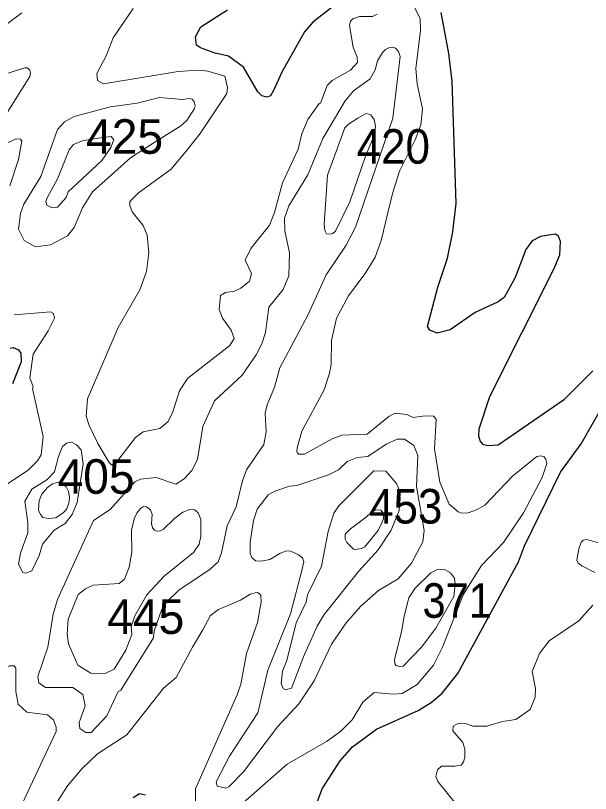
# Model space of a CAD drawing. Extents: x 499.9 to 555.3, y 9281.5 to 9336.8.
# Drawn here: x 543.063 to 545.724, y 9322.551 to 9326.154 of the extents above; entities that cross this region are included whole.
import ezdxf

# ---------------------------------------------------------------- set-up
doc = ezdxf.new("R2010")
doc.units = 0
doc.header["$LTSCALE"] = 0.064
doc.layers.add('1', color=7, linetype='Continuous', lineweight=25)
doc.layers.add('2', color=7, linetype='Continuous', lineweight=13)
doc.layers.add('21', color=7, linetype='Continuous')

msp = doc.modelspace()

# ---------------------------------------------------------------- linework, layer by layer
at = {"layer": '1'}
for points in [[(544.5287, 9326.1933), (544.439, 9326.1227), (544.4008, 9326.0781), (544.2953, 9325.8912), (544.2576, 9325.8066), (544.2426, 9325.7829), (544.2262, 9325.7766), (544.2022, 9325.7818), (544.184, 9325.8005), (544.1174, 9325.9155), (544.0486, 9325.966), (543.9862, 9325.9797), (543.9197, 9326.0039), (543.9011, 9326.0169), (543.8952, 9326.0548), (543.9209, 9326.1023), (544.0435, 9326.1811)], [(545.7352, 9324.509), (545.5991, 9324.372), (545.2972, 9324.1635), (545.2514, 9324.1604), (545.2286, 9324.1654), (545.213, 9324.1836), (545.2065, 9324.2059), (545.2085, 9324.2395), (545.2583, 9324.39), (545.5537, 9324.9796), (545.5816, 9325.0461), (545.5847, 9325.108), (545.5754, 9325.132), (545.561, 9325.1422), (545.4933, 9325.1313), (545.4539, 9325.1113), (545.4249, 9325.0702), (545.375, 9324.9409), (545.3242, 9324.8485), (545.2967, 9324.8288), (545.1909, 9324.7782), (545.0747, 9324.6981), (545.0144, 9324.6828), (544.9803, 9324.6969), (544.9702, 9324.7136), (545.0173, 9324.8955), (545.0622, 9325.0302), (545.0866, 9325.1526), (545.1026, 9325.2828), (545.0835, 9325.8505), (545.069, 9325.9787), (545.0325, 9326.1688)], [(543.0383, 9324.6136), (543.0524, 9324.6164), (543.076, 9324.6054), (543.088, 9324.5903), (543.0886, 9324.5509), (543.0492, 9324.448)], [(544.4325, 9322.4383), (544.482, 9322.5719), (544.5652, 9322.7015), (544.622, 9322.7675), (544.7343, 9322.8484), (544.9268, 9322.936), (544.9864, 9322.973), (545.0369, 9323.0157), (545.11, 9323.106), (545.3913, 9323.6241), (545.4194, 9323.6987), (545.5845, 9324.0386), (545.6808, 9324.1706), (545.7827, 9324.3488)], [(543.6076, 9322.5331), (543.6373, 9322.5512), (543.6641, 9322.5446)]]:
    msp.add_lwpolyline(points, dxfattribs=at)
at = {"layer": '2'}
for points in [[(544.6249, 9326.0083), (544.644, 9325.9618), (544.6453, 9325.9361), (544.6139, 9325.9016), (544.5287, 9325.8531), (544.5047, 9325.8303), (544.4743, 9325.7484), (544.4675, 9325.7462), (544.4153, 9325.6726), (544.3882, 9325.6061), (544.3716, 9325.5345), (544.2984, 9325.379), (544.261, 9325.2417), (544.2389, 9325.1826), (544.152, 9325.0754), (544.1263, 9325.0216), (544.1552, 9324.9599), (544.1461, 9324.9233), (544.1051, 9324.8911), (544.076, 9324.8782), (544.0341, 9324.8713), (544.0116, 9324.8567), (544.0051, 9324.792), (544.0205, 9324.7524), (544.0604, 9324.6974), (544.0755, 9324.6576), (544.0553, 9324.6251), (543.8601, 9324.4739), (543.8213, 9324.4156), (543.7897, 9324.3139), (543.7672, 9324.2719), (543.7305, 9324.2417), (543.6535, 9324.2256), (543.6175, 9324.1996), (543.5404, 9324.0988), (543.5282, 9324.0809), (543.5194, 9324.0733), (543.5063, 9324.0731), (543.4955, 9324.0837), (543.4436, 9324.1714), (543.4032, 9324.2551), (543.3901, 9324.2979), (543.3964, 9324.3791), (543.5385, 9324.7088), (543.6383, 9324.8829), (543.6686, 9324.9688), (543.6797, 9325.0547), (543.6719, 9325.1368), (543.653, 9325.1813), (543.6026, 9325.2453), (543.5926, 9325.274), (543.5923, 9325.2927), (543.6316, 9325.3322), (543.7828, 9325.4422), (543.8589, 9325.5332), (543.9172, 9325.6079), (544.0415, 9325.7929), (544.0439, 9325.8205), (544.0311, 9325.8725), (543.9527, 9325.8964), (543.9107, 9325.9011), (543.8159, 9325.8943), (543.4697, 9325.8381), (543.4428, 9325.8526), (543.4396, 9325.8856), (543.482, 9325.9677), (543.5155, 9326.0503), (543.6067, 9326.1869)], [(544.0272, 9322.4295), (544.3203, 9322.6869), (544.5019, 9322.7911), (544.567, 9322.8383), (544.6203, 9322.8919), (544.6699, 9322.9744), (544.7225, 9323.0191), (544.8106, 9323.0113), (544.8519, 9323.0144), (544.9211, 9323.0558), (544.9971, 9323.1451), (545.0388, 9323.2283), (545.1364, 9323.4748), (545.2199, 9323.6074), (545.3218, 9323.7129), (545.4141, 9323.8508), (545.5005, 9324.0139), (545.5223, 9324.0791), (545.5171, 9324.0972), (545.5096, 9324.1106), (545.4942, 9324.1152), (545.4753, 9324.1117), (545.3631, 9324.0213), (545.2347, 9323.8866), (545.1965, 9323.8643), (545.1583, 9323.851), (545.1265, 9323.85), (545.1111, 9323.8561), (545.0692, 9323.8916), (545.0269, 9323.9927), (545.0024, 9324.1475), (545.0102, 9324.2847), (544.9973, 9324.2984), (544.9578, 9324.3002), (544.9034, 9324.2924), (544.8742, 9324.3068), (544.8191, 9324.3118), (544.7908, 9324.2976), (544.6911, 9324.2145), (544.5727, 9324.2111), (544.5281, 9324.1937), (544.4003, 9324.1221), (544.376, 9324.1223), (544.3679, 9324.1275), (544.3655, 9324.1354), (544.366, 9324.1521), (544.3885, 9324.2291), (544.4911, 9324.4207), (544.5167, 9324.497), (544.5233, 9324.5377), (544.525, 9324.649), (544.5488, 9324.7523), (544.6035, 9324.8559), (544.685, 9324.9639), (544.727, 9325.0356), (544.7556, 9325.112), (544.807, 9325.3302), (544.8398, 9325.4328), (544.9122, 9325.5784), (544.9388, 9325.6476), (544.9466, 9325.7225), (544.9212, 9325.8378), (544.9164, 9325.9093), (544.9369, 9326.0854), (544.9352, 9326.1401), (544.9099, 9326.1911)], [(543.0925, 9326.166), (542.9556, 9326.0655), (542.8864, 9326.0303), (542.8583, 9326.0273), (542.7971, 9326.0367), (542.7721, 9326.0767), (542.7648, 9326.1236), (542.7679, 9326.1728)], [(544.7369, 9326.1597), (544.7154, 9326.1502)], [(544.7154, 9326.1502), (544.6555, 9326.1496), (544.6243, 9326.1388), (544.6131, 9326.1285), (544.608, 9326.1082), (544.6249, 9326.0083)], [(543.0129, 9325.8824), (543.1055, 9325.9126), (543.1174, 9325.9122), (543.1277, 9325.9037), (543.132, 9325.8891), (543.1295, 9325.8713), (542.9964, 9325.6604)], [(542.9896, 9325.5494), (543.0656, 9325.5836), (543.0865, 9325.581), (543.0928, 9325.5724), (543.0762, 9325.487), (543.0366, 9325.3659)], [(543.0567, 9324.7671), (543.2253, 9324.781), (543.2391, 9324.7747), (543.243, 9324.7526), (543.2143, 9324.6936), (543.1445, 9324.5851), (543.1296, 9324.4761), (543.1438, 9324.4343), (543.1407, 9324.4261), (543.1903, 9324.2037)], [(543.1903, 9324.2037), (543.1816, 9324.1197), (543.1644, 9324.0919), (543.1233, 9324.0494), (542.996, 9323.9649), (542.9687, 9323.9204)], [(545.7822, 9323.7057), (545.7065, 9323.7266), (545.69, 9323.7244), (545.6803, 9323.7154), (545.6699, 9323.6836), (545.6616, 9323.6321), (545.6674, 9323.6181), (545.6838, 9323.605), (545.7438, 9323.5744)], [(543.9305, 9323.3094), (543.9649, 9323.3746), (544.0027, 9323.4024), (544.1043, 9323.447), (544.1493, 9323.4742), (544.1715, 9323.4803), (544.1832, 9323.4821), (544.1909, 9323.4775), (544.1975, 9323.4685), (544.1998, 9323.4369), (544.1827, 9323.3422), (544.132, 9323.1998), (544.105, 9323.0576), (544.0884, 9323.0084), (543.8951, 9322.5727), (543.8946, 9322.4294)], [(545.7347, 9323.4226), (545.6708, 9323.3506), (545.5334, 9323.2573), (545.4874, 9323.1998), (545.4544, 9323.1157), (545.4701, 9323.0366), (545.4687, 9322.997), (545.4449, 9322.9402), (545.3779, 9322.8936), (545.3175, 9322.8847), (545.2442, 9322.8633), (545.1802, 9322.863), (545.1503, 9322.8742), (545.1095, 9322.8744)], [(543.222, 9322.4589), (543.3037, 9322.5872), (543.3715, 9322.6661), (543.4427, 9322.7342), (543.5773, 9322.823), (543.7482, 9323.0382), (543.8063, 9323.0888), (543.8821, 9323.2283), (543.9305, 9323.3094)], [(542.2021, 9322.5045), (542.3336, 9322.6297), (542.5889, 9322.807), (542.7846, 9322.9614), (542.9205, 9323.052), (542.9907, 9323.1239), (543.0365, 9323.1426), (543.0571, 9323.1429), (543.0637, 9323.131), (543.0648, 9323.0234), (543.0745, 9322.9649), (543.115, 9322.9271), (543.2102, 9322.9155), (543.2393, 9322.8921), (543.2515, 9322.8584), (543.251, 9322.8379), (542.9945, 9322.2935)], [(545.1095, 9322.8744), (545.0887, 9322.8627), (545.0874, 9322.8416), (545.1331, 9322.7868), (545.1418, 9322.7556), (545.142, 9322.7177)], [(545.142, 9322.7177), (545.1367, 9322.6974), (545.1251, 9322.682), (545.0962, 9322.6771), (545.0344, 9322.6776), (545.0153, 9322.6608), (545.009, 9322.63), (545.0177, 9322.6071), (545.0944, 9322.5113)]]:
    msp.add_lwpolyline(points, dxfattribs=at)
for points in [[(544.3071, 9325.2162), (544.3283, 9325.2734), (544.4153, 9325.4163), (544.4857, 9325.5851), (544.5889, 9325.7586), (544.6271, 9325.8059), (544.705, 9325.8608), (544.7271, 9325.9022), (544.7385, 9325.9435), (544.7617, 9325.9836), (544.775, 9325.9965), (544.7933, 9326.0059), (544.8076, 9326.0081), (544.8213, 9326.0036), (544.8354, 9325.9871), (544.843, 9325.965), (544.8097, 9325.6786), (544.6365, 9325.1733), (544.5937, 9325.0904), (544.5006, 9324.9538), (544.4174, 9324.7699), (544.2868, 9324.5222), (544.262, 9324.4333), (544.2271, 9324.3506), (544.2184, 9324.3132), (544.2223, 9324.2264), (544.2129, 9324.1673), (544.1326, 9324.0502), (544.113, 9323.9987), (544.0843, 9323.8792), (544.0427, 9323.791), (544.0168, 9323.6662), (544.0003, 9323.6241), (543.964, 9323.5901), (543.8183, 9323.4934), (543.7621, 9323.4371), (543.7384, 9323.4004), (543.7048, 9323.3042), (543.7008, 9323.2717), (543.551, 9323.0296), (543.5379, 9323.0231), (543.4851, 9322.9114), (543.4125, 9322.8336), (543.388, 9322.8335), (543.3603, 9322.8524), (543.3569, 9322.8794), (543.385, 9322.9563), (543.3751, 9323.01), (543.328, 9323.0412), (543.2011, 9323.0412), (543.1715, 9323.063), (543.1661, 9323.0931), (543.212, 9323.2284), (543.2374, 9323.3812), (543.2573, 9323.4488), (543.4236, 9323.8151), (543.5015, 9323.8665), (543.6149, 9323.9949), (543.6409, 9324.007), (543.7141, 9324.0152), (543.8055, 9323.9841), (543.8441, 9324.0081), (543.8786, 9324.0474), (543.9045, 9324.0985), (543.93, 9324.2502), (543.9844, 9324.3692), (544.1115, 9324.4888), (544.1759, 9324.583), (544.2029, 9324.6339), (544.2191, 9324.6855), (544.2351, 9324.8026), (544.3019, 9324.8845), (544.3274, 9324.9487), (544.3306, 9325.0547), (544.3101, 9325.1566)], [(543.4187, 9325.3376), (543.5944, 9325.4955), (543.6954, 9325.5603), (543.8277, 9325.6437), (543.8556, 9325.6685), (543.8917, 9325.7229), (543.8942, 9325.7359), (543.8903, 9325.7543), (543.8798, 9325.7672), (543.8679, 9325.7694), (543.8334, 9325.7646), (543.7291, 9325.774), (543.6265, 9325.7485), (543.5032, 9325.7311), (543.3338, 9325.6862), (543.2894, 9325.6621), (543.2577, 9325.6269), (543.1798, 9325.4082), (543.1018, 9325.28), (543.0857, 9325.2376), (543.0771, 9325.1651), (543.1028, 9325.1117), (543.1548, 9325.0827), (543.2244, 9325.0925), (543.304, 9325.1345), (543.3338, 9325.172), (543.3733, 9325.2632)], [(544.6824, 9325.5024), (544.7221, 9325.5978), (544.7284, 9325.6421), (544.7226, 9325.6727), (544.707, 9325.6947), (544.6862, 9325.7007), (544.6476, 9325.6781), (544.6033, 9325.6508), (544.5878, 9325.6332), (544.5064, 9325.4142), (544.4915, 9325.1877), (544.495, 9325.1592), (544.5028, 9325.1433), (544.5163, 9325.141), (544.5316, 9325.1453), (544.5444, 9325.1559), (544.6102, 9325.2919)], [(543.4619, 9325.4825), (543.5043, 9325.5435), (543.5173, 9325.5776), (543.5059, 9325.5943), (543.4456, 9325.5854), (543.3706, 9325.5731), (543.3308, 9325.5567), (543.3107, 9325.5326), (543.2591, 9325.401), (543.2073, 9325.3062), (543.2036, 9325.2925), (543.2075, 9325.2763), (543.2318, 9325.2639), (543.2573, 9325.2667), (543.2965, 9325.3111), (543.3065, 9325.3369)], [(543.242, 9323.7709), (543.2921, 9323.8008), (543.3243, 9323.8436), (543.3479, 9323.8985), (543.3756, 9324.0775), (543.3664, 9324.1421), (543.345, 9324.1654), (543.3216, 9324.1775), (543.2994, 9324.1728), (543.28, 9324.1579), (543.2612, 9324.1125), (543.2438, 9324.0411), (543.2084, 9324.0032), (543.1384, 9323.9609), (543.1054, 9323.9048), (543.1195, 9323.8062), (543.1194, 9323.7579), (543.0862, 9323.6637), (543.0769, 9323.6136), (543.0974, 9323.575), (543.1099, 9323.5719), (543.1376, 9323.5823), (543.172, 9323.6534), (543.1882, 9323.7051)], [(544.3362, 9323.3824), (544.3894, 9323.5892), (544.3969, 9323.6249), (544.391, 9323.6417), (544.3729, 9323.6563), (544.3371, 9323.6737), (544.316, 9323.6745), (544.2861, 9323.6621), (544.2404, 9323.6346), (544.1994, 9323.6271), (544.1737, 9323.629), (544.1559, 9323.6432), (544.1495, 9323.6631), (544.1493, 9323.7146), (544.165, 9323.8157), (544.1816, 9323.8681), (544.2317, 9323.9337), (544.2623, 9323.951), (544.3307, 9323.9739), (544.3656, 9323.9776), (544.5121, 9324.0267), (544.5575, 9324.0501), (544.5982, 9324.0885), (544.6435, 9324.1077), (544.6942, 9324.1115), (544.7789, 9324.1693), (544.8286, 9324.1913), (544.8638, 9324.1919), (544.907, 9324.1627), (544.9256, 9324.1163), (544.918, 9323.9726), (544.9544, 9323.7695), (544.9474, 9323.716), (544.8952, 9323.6177), (544.834, 9323.5449), (544.7431, 9323.4905), (544.6618, 9323.4186), (544.5929, 9323.3421), (544.5249, 9323.2419), (544.4456, 9323.0724), (544.3736, 9322.9667), (544.2752, 9322.8598), (544.1185, 9322.6516), (544.0496, 9322.582), (544.0361, 9322.5754), (543.9967, 9322.5849), (543.9909, 9322.6043), (544.0532, 9322.7232), (544.1841, 9322.9253), (544.2311, 9323.1222)], [(544.479, 9323.6041), (544.5105, 9323.7639), (544.5364, 9323.8487), (544.5592, 9323.8831), (544.7211, 9324.0447), (544.7761, 9324.0437), (544.8255, 9323.9867), (544.8369, 9323.9605), (544.843, 9323.9184), (544.8382, 9323.8612), (544.8017, 9323.7703), (544.7421, 9323.6794), (544.65, 9323.5794), (544.491, 9323.3797), (544.4597, 9323.3263), (544.3963, 9323.1837), (544.3409, 9323.0385), (544.3127, 9323.0307), (544.3019, 9323.0374), (544.2928, 9323.0599), (544.2986, 9323.1174), (544.3179, 9323.1671), (544.3621, 9323.3418), (544.4083, 9323.4366), (544.4137, 9323.471)], [(543.1899, 9323.8298), (543.2152, 9323.8243), (543.2499, 9323.8282), (543.2846, 9323.8527), (543.2996, 9323.8701), (543.3114, 9323.9016), (543.313, 9323.9229), (543.3083, 9323.949), (543.2965, 9323.9719), (543.2807, 9323.9845), (543.2554, 9323.9908), (543.2333, 9323.9845), (543.2112, 9323.9679), (543.1852, 9323.9379), (543.1726, 9323.9072), (543.1686, 9323.863), (543.1789, 9323.8425)], [(543.6016, 9323.6683), (543.5998, 9323.7698), (543.6123, 9323.8237), (543.6249, 9323.8499), (543.6407, 9323.8705), (543.6547, 9323.8796), (543.6696, 9323.8789), (543.688, 9323.8645), (543.696, 9323.8426), (543.6925, 9323.8008), (543.6964, 9323.7819), (543.7059, 9323.7709), (543.718, 9323.7665), (543.7326, 9323.7675), (543.7469, 9323.7732), (543.7998, 9323.8261), (543.8374, 9323.8546), (543.8691, 9323.8657), (543.891, 9323.8648), (543.9075, 9323.8507), (543.9198, 9323.8197), (543.92, 9323.7433), (543.9135, 9323.7052), (543.8868, 9323.6672), (543.7523, 9323.5598), (543.6707, 9323.4711), (543.6154, 9323.3738), (543.5987, 9323.3232), (543.6013, 9323.2873), (543.5731, 9323.2146), (543.5194, 9323.1266), (543.4784, 9323.1066), (543.4108, 9323.1085), (543.351, 9323.1446), (543.3081, 9323.2435), (543.3026, 9323.2882), (543.3064, 9323.3581), (543.3523, 9323.4722), (543.3863, 9323.4992), (543.4222, 9323.5159), (543.5429, 9323.5235), (543.5677, 9323.5439), (543.5887, 9323.5993)], [(544.6862, 9323.8309), (544.6127, 9323.7764), (544.595, 9323.7586), (544.5891, 9323.7515), (544.5879, 9323.729), (544.5962, 9323.7136), (544.627, 9323.6828), (544.6353, 9323.6804), (544.6637, 9323.6863), (544.6803, 9323.6935), (544.7419, 9323.7693), (544.7573, 9323.8013), (544.7667, 9323.8238), (544.7644, 9323.8486), (544.7537, 9323.8629), (544.7324, 9323.8652), (544.7087, 9323.8522)], [(544.9422, 9323.2283), (545.0078, 9323.3163), (545.0918, 9323.4635), (545.0977, 9323.5198), (545.0944, 9323.549), (545.0759, 9323.5724), (545.0515, 9323.5869), (545.0165, 9323.5878), (544.9851, 9323.5734), (544.9122, 9323.5019), (544.8831, 9323.4576), (544.8621, 9323.373), (544.8496, 9323.299), (544.8164, 9323.171), (544.8179, 9323.1511), (544.8239, 9323.1433), (544.8394, 9323.139), (544.857, 9323.1413)]]:
    msp.add_lwpolyline(points, close=True, dxfattribs=at)

# ---------------------------------------------------------------- texts
at = {"layer": '21'}
for s, p in [('425', (543.3892, 9325.5138)), ('405', (543.2571, 9323.9393)), ('445', (543.4869, 9323.29))]:
    msp.add_text(s, height=0.16, dxfattribs=at).set_placement(p)
for s, width, p in [('420', 0.95, (544.6419, 9325.4678)), ('453', 0.95, (544.6994, 9323.8014)), ('371', 0.9, (544.9465, 9323.3647))]:
    msp.add_text(s, height=0.16, dxfattribs=dict(at, width=width)).set_placement(p)

doc.saveas('drawing.dxf')
